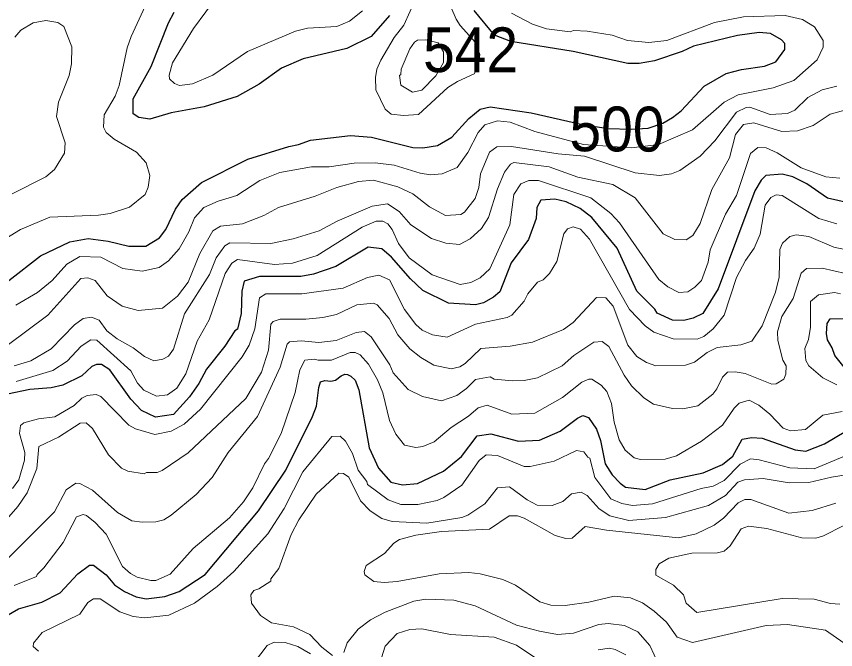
# Model space of a CAD drawing. Extents: x 673.3 to 698.5, y 6984.3 to 7012.3.
# Drawn here: x 690.238 to 691.701, y 6994.327 to 6995.457 of the extents above; entities that cross this region are included whole.
import ezdxf
from ezdxf.enums import TextEntityAlignment as Align

# ---------------------------------------------------------------- set-up
doc = ezdxf.new("R2010")
doc.units = 0
doc.header["$LTSCALE"] = 0.032
doc.layers.add('1', color=7, linetype='Continuous', lineweight=25)
doc.layers.add('2', color=7, linetype='Continuous', lineweight=13)
doc.layers.add('21', color=7, linetype='Continuous')
doc.layers.add('61', color=7, linetype='Continuous')

msp = doc.modelspace()

# ---------------------------------------------------------------- linework, layer by layer
at = {"layer": '1'}
for points in [[(690.9046, 6995.4588), (690.8716, 6995.4215), (690.8281, 6995.4003), (690.7503, 6995.3815), (690.7115, 6995.3646), (690.6715, 6995.3363), (690.6323, 6995.3145), (690.5737, 6995.2958), (690.5143, 6995.2851), (690.4766, 6995.2741), (690.4569, 6995.2766), (690.4465, 6995.2836), (690.4467, 6995.3102), (690.4786, 6995.3676), (690.5096, 6995.4458), (690.52, 6995.4649)], [(691.5326, 6995.3626), (691.5737, 6995.3684), (691.5942, 6995.3762), (691.61, 6995.3981), (691.6102, 6995.4089), (691.6045, 6995.4157), (691.5845, 6995.4269), (691.5646, 6995.4288), (691.5255, 6995.423), (691.4474, 6995.4043), (691.4271, 6995.3944), (691.3777, 6995.3779), (691.3504, 6995.3735), (691.3298, 6995.3735), (691.2321, 6995.3947), (691.1211, 6995.4128), (691.0919, 6995.4241), (691.0558, 6995.4676)], [(690.2245, 6994.9859), (690.2815, 6995.0299), (690.3338, 6995.0547), (690.3662, 6995.0607), (690.402, 6995.0561), (690.4389, 6995.0469), (690.4691, 6995.0471), (690.4934, 6995.0621), (690.5047, 6995.0768), (690.5224, 6995.1131), (690.534, 6995.1301), (690.5686, 6995.1608), (690.6514, 6995.2023), (690.7245, 6995.2253), (690.7418, 6995.2284), (690.7631, 6995.2361), (690.8347, 6995.2447), (690.8724, 6995.2415), (690.946, 6995.2235), (690.9639, 6995.2228), (690.9903, 6995.2268), (691.0157, 6995.2416), (691.0458, 6995.2748), (691.066, 6995.2917), (691.0839, 6995.2959), (691.1572, 6995.2852), (691.249, 6995.2643), (691.2949, 6995.2569), (691.3361, 6995.2562), (691.3662, 6995.258), (691.3923, 6995.2664), (691.4099, 6995.2769), (691.4251, 6995.289), (691.4664, 6995.333), (691.5055, 6995.3552), (691.5326, 6995.3626)], [(691.7233, 6995.1244), (691.6866, 6995.1325), (691.6493, 6995.1584), (691.6246, 6995.1707), (691.6054, 6995.1755), (691.5763, 6995.173), (691.5681, 6995.1651), (691.5567, 6995.1457), (691.4912, 6994.9709), (691.4641, 6994.927), (691.4468, 6994.9184), (691.4297, 6994.9142), (691.4099, 6994.915), (691.3823, 6994.9272), (691.3781, 6994.9344), (691.3462, 6994.967), (691.3109, 6995.0435), (691.2656, 6995.0983), (691.2446, 6995.1144), (691.2196, 6995.1265), (691.1998, 6995.1307), (691.1743, 6995.1292), (691.1673, 6995.116), (691.1664, 6995.0965), (691.1525, 6995.0591), (691.1217, 6995.0175), (691.1013, 6994.9653), (691.0901, 6994.9558), (691.072, 6994.9461), (691.0578, 6994.9426), (691.0095, 6994.9453), (690.9639, 6994.9677), (690.942, 6994.9887), (690.908, 6995.0275), (690.8906, 6995.0425), (690.866, 6995.0451), (690.8087, 6995.0109), (690.7685, 6994.9972), (690.7463, 6994.9929), (690.6721, 6994.9931), (690.645, 6994.9844), (690.6404, 6994.9665), (690.6395, 6994.9268), (690.6331, 6994.8989), (690.628, 6994.8958), (690.6102, 6994.8685), (690.5779, 6994.8276), (690.564, 6994.802), (690.547, 6994.7783), (690.5187, 6994.7463), (690.4865, 6994.7415), (690.4614, 6994.7536), (690.4427, 6994.774), (690.4053, 6994.8265), (690.3903, 6994.8359), (690.3813, 6994.8359), (690.373, 6994.8321), (690.3549, 6994.8156), (690.321, 6994.7987), (690.3004, 6994.7944), (690.2619, 6994.7912), (690.222, 6994.7827)], [(691.7164, 6994.8308), (691.6993, 6994.852), (691.6949, 6994.8658), (691.6864, 6994.8798), (691.6844, 6994.8911), (691.686, 6994.9089), (691.6914, 6994.9174), (691.7197, 6994.9181)], [(690.4134, 6994.4422), (690.4313, 6994.4302), (690.4521, 6994.421), (690.4699, 6994.4174), (690.503, 6994.4217), (690.529, 6994.4305), (690.5754, 6994.4609), (690.6704, 6994.5745), (690.7195, 6994.6473), (690.7671, 6994.7428), (690.774, 6994.7614), (690.7781, 6994.795), (690.7813, 6994.8049), (690.7887, 6994.8073), (690.7998, 6994.8059), (690.8082, 6994.8077), (690.8179, 6994.8156), (690.8244, 6994.8184), (690.8295, 6994.8177), (690.8356, 6994.8152), (690.8428, 6994.8077), (690.8497, 6994.7908), (690.8678, 6994.687), (690.8845, 6994.6505), (690.9067, 6994.6259), (690.9275, 6994.621), (690.9545, 6994.6232), (691.0006, 6994.6455), (691.0328, 6994.6714), (691.0606, 6994.7087), (691.085, 6994.7121), (691.1349, 6994.6991), (691.1724, 6994.7008), (691.2093, 6994.7169), (691.2399, 6994.7402), (691.2493, 6994.7446), (691.2598, 6994.741), (691.2742, 6994.7205), (691.2812, 6994.7002), (691.2896, 6994.6582), (691.3019, 6994.6386), (691.316, 6994.6236), (691.3258, 6994.617), (691.361, 6994.6128), (691.4053, 6994.6299), (691.4644, 6994.6424), (691.4987, 6994.6572), (691.5173, 6994.6722), (691.5343, 6994.7026), (691.5516, 6994.7056), (691.5695, 6994.704), (691.6285, 6994.6836), (691.6477, 6994.6813), (691.6808, 6994.6941), (691.7191, 6994.7168)], [(690.2033, 6994.3776), (690.2422, 6994.3994), (690.2835, 6994.4117), (690.3164, 6994.4283), (690.3477, 6994.4619), (690.3686, 6994.4776), (690.3758, 6994.4775), (690.3985, 6994.4602), (690.4134, 6994.4422)]]:
    msp.add_lwpolyline(points, dxfattribs=at)
at = {"layer": '2'}
for points in [[(691.0626, 6995.3684), (691.0654, 6995.3894), (691.0581, 6995.4106), (691.0306, 6995.4408), (691.0233, 6995.4522), (691.0043, 6995.4972), (690.9997, 6995.5029), (690.971, 6995.5045), (690.9525, 6995.4925), (690.9302, 6995.4418), (690.9127, 6995.4196), (690.8887, 6995.3791), (690.8819, 6995.3631), (690.8792, 6995.3485), (690.8802, 6995.3264), (690.8967, 6995.2916), (690.9071, 6995.2827), (690.9293, 6995.2806), (690.9564, 6995.282), (691.0085, 6995.3301), (691.0258, 6995.341), (691.0556, 6995.3548)], [(690.9244, 6995.3343), (690.9222, 6995.352), (690.9245, 6995.3533), (690.9253, 6995.3631), (690.9407, 6995.3993), (690.9488, 6995.4112), (690.9543, 6995.4149), (690.9691, 6995.4157), (690.9911, 6995.4101), (691.001, 6995.3943), (691.001, 6995.3751), (690.9872, 6995.3514), (690.9619, 6995.3256), (690.9453, 6995.3221)]]:
    msp.add_lwpolyline(points, close=True, dxfattribs=at)
for points in [[(690.8564, 6995.4673), (690.8327, 6995.4488), (690.8102, 6995.4393), (690.7581, 6995.4361), (690.7363, 6995.4307), (690.651, 6995.3945), (690.5887, 6995.3521), (690.5529, 6995.3367), (690.5295, 6995.3337), (690.5203, 6995.3376), (690.5115, 6995.3459), (690.5109, 6995.3526), (690.5171, 6995.3745), (690.5542, 6995.4356), (690.5987, 6995.4957)], [(690.4683, 6995.4758), (690.4428, 6995.4217), (690.436, 6995.4014), (690.4219, 6995.334), (690.4147, 6995.3149), (690.3951, 6995.2816), (690.3936, 6995.2595), (690.3987, 6995.2502), (690.4129, 6995.2379), (690.4525, 6995.2152), (690.4701, 6995.1958), (690.4766, 6995.1732), (690.4734, 6995.1523), (690.4683, 6995.1391), (690.4401, 6995.1165), (690.4054, 6995.1055), (690.3849, 6995.1023), (690.2976, 6995.0989), (690.2454, 6995.0769), (690.2114, 6995.0559)], [(691.0972, 6995.2707), (691.1197, 6995.2684), (691.1637, 6995.2521), (691.2507, 6995.2284), (691.3363, 6995.2228), (691.3847, 6995.2286), (691.4452, 6995.2547), (691.5017, 6995.3042), (691.5269, 6995.3171), (691.5895, 6995.3295), (691.6262, 6995.3431), (691.6678, 6995.3797), (691.6784, 6995.4024), (691.6785, 6995.4141), (691.6633, 6995.4388), (691.6417, 6995.4515), (691.6106, 6995.4589), (691.5362, 6995.4564), (691.4848, 6995.4466), (691.3998, 6995.4141), (691.3671, 6995.4109), (691.3292, 6995.414), (691.3017, 6995.4241), (691.2572, 6995.4312), (691.2327, 6995.432), (691.2272, 6995.4296), (691.1847, 6995.435), (691.1594, 6995.4433), (691.1219, 6995.4628)], [(690.2307, 6995.1405), (690.2907, 6995.1708), (690.3064, 6995.1837), (690.3243, 6995.2133), (690.325, 6995.2314), (690.3097, 6995.2784), (690.3131, 6995.3043), (690.3322, 6995.3516), (690.3364, 6995.3728), (690.3373, 6995.4027), (690.3228, 6995.4391), (690.3121, 6995.4466), (690.291, 6995.45), (690.2684, 6995.4459), (690.2459, 6995.4325), (690.2355, 6995.4203)], [(691.7028, 6995.3326), (691.677, 6995.3261), (691.6513, 6995.3125), (691.6282, 6995.2896), (691.6147, 6995.2838), (691.5838, 6995.2822), (691.5479, 6995.2953), (691.541, 6995.2948), (691.524, 6995.2863), (691.4855, 6995.2351), (691.459, 6995.2075), (691.4225, 6995.1819), (691.408, 6995.1763), (691.3864, 6995.1732), (691.3431, 6995.178), (691.2523, 6995.208), (691.2055, 6995.2122), (691.122, 6995.2251), (691.096, 6995.2243), (691.0828, 6995.2148), (691.067, 6995.176), (691.0637, 6995.1519), (691.0572, 6995.1323), (691.0384, 6995.1078), (691.0317, 6995.1039), (691.0044, 6995.1017), (690.9755, 6995.117), (690.9462, 6995.1407), (690.9195, 6995.1533), (690.8757, 6995.1649), (690.8493, 6995.1624), (690.8102, 6995.1518), (690.7717, 6995.1366), (690.7064, 6995.116), (690.6799, 6995.1021), (690.6418, 6995.087), (690.6024, 6995.0826), (690.5891, 6995.0746), (690.5659, 6995.034), (690.545, 6994.9826), (690.5261, 6994.9579), (690.499, 6994.9362), (690.4555, 6994.9321), (690.4268, 6994.9399), (690.4003, 6994.9586), (690.3786, 6994.9859), (690.3656, 6994.9906), (690.3531, 6994.9891), (690.2945, 6994.9241), (690.2219, 6994.8697)], [(690.234, 6994.8335), (690.264, 6994.8425), (690.3002, 6994.8638), (690.342, 6994.9065), (690.3571, 6994.9177), (690.3723, 6994.9205), (690.3862, 6994.9148), (690.3995, 6994.896), (690.4183, 6994.8814), (690.4467, 6994.8656), (690.4667, 6994.8502), (690.4835, 6994.8425), (690.4999, 6994.845), (690.51, 6994.8506), (690.5188, 6994.8634), (690.5383, 6994.9265), (690.583, 6994.9966), (690.5948, 6995.0265), (690.6103, 6995.0476), (690.6193, 6995.053), (690.6926, 6995.0518), (690.7326, 6995.0599), (690.779, 6995.0743), (690.8111, 6995.0915), (690.8734, 6995.1183), (690.9006, 6995.1226), (690.9218, 6995.1089), (690.9424, 6995.0853), (690.9793, 6995.0606), (691.0048, 6995.0522), (691.0296, 6995.0501), (691.0486, 6995.06), (691.0688, 6995.0789), (691.081, 6995.0984), (691.0973, 6995.1496), (691.1099, 6995.179), (691.1204, 6995.1937), (691.1263, 6995.1966), (691.1897, 6995.1886), (691.2405, 6995.1702), (691.3034, 6995.1571), (691.3431, 6995.1331), (691.3927, 6995.0691), (691.4138, 6995.0589), (691.4341, 6995.0583), (691.4462, 6995.0662), (691.4588, 6995.0878), (691.4798, 6995.1484), (691.5114, 6995.205), (691.5221, 6995.2462), (691.5364, 6995.2643), (691.5549, 6995.2675), (691.6051, 6995.2521), (691.6327, 6995.2528), (691.661, 6995.2628), (691.6914, 6995.2828), (691.724, 6995.2918)], [(690.2369, 6994.9416), (690.2761, 6994.9643), (690.3021, 6994.9855), (690.3282, 6995.0148), (690.3513, 6995.0289), (690.3888, 6995.0272), (690.4283, 6995.0074), (690.4625, 6995.0025), (690.4932, 6995.0087), (690.51, 6995.0208), (690.529, 6995.0423), (690.5459, 6995.0726), (690.5561, 6995.0975), (690.5727, 6995.116), (690.5982, 6995.1272), (690.632, 6995.1374), (690.6731, 6995.1644), (690.7083, 6995.1784), (690.7652, 6995.1886), (690.7966, 6995.1886), (690.8412, 6995.195), (690.8789, 6995.1959), (690.9128, 6995.1918), (690.9589, 6995.1776), (690.9777, 6995.1747), (690.9982, 6995.1764), (691.0254, 6995.1877), (691.0444, 6995.2144), (691.0627, 6995.2502), (691.0747, 6995.2635), (691.0972, 6995.2707)], [(691.7085, 6995.1682), (691.6834, 6995.1708), (691.6393, 6995.1871), (691.5964, 6995.2137), (691.5767, 6995.2225), (691.5619, 6995.2232), (691.5492, 6995.2126), (691.5242, 6995.1378), (691.5042, 6995.1044), (691.4767, 6995.0403), (691.4735, 6995.0186), (691.4612, 6994.986), (691.4498, 6994.9736), (691.4373, 6994.9658), (691.4209, 6994.9646), (691.4015, 6994.9745), (691.3851, 6994.9878), (691.315, 6995.0889), (691.2997, 6995.1056), (691.2641, 6995.1331), (691.1703, 6995.1645), (691.1529, 6995.1642), (691.1388, 6995.1584), (691.1266, 6995.1393), (691.1191, 6995.0851), (691.0834, 6995.0064), (691.066, 6994.9905), (691.0493, 6994.9823), (691.0308, 6994.9785), (690.9806, 6994.9961), (690.9396, 6995.0262), (690.9202, 6995.0516), (690.9091, 6995.0767), (690.9015, 6995.0869), (690.8927, 6995.0916), (690.8805, 6995.0916), (690.8555, 6995.0807), (690.7753, 6995.0304), (690.7313, 6995.0166), (690.6988, 6995.0143), (690.6331, 6995.0233), (690.6226, 6995.0169), (690.6111, 6994.9984), (690.5824, 6994.9155), (690.5609, 6994.8774), (690.5406, 6994.8189), (690.5246, 6994.7935), (690.5082, 6994.7817), (690.4881, 6994.779), (690.4655, 6994.7902), (690.4542, 6994.8026), (690.4424, 6994.8245), (690.3817, 6994.879), (690.3713, 6994.8799), (690.354, 6994.8684), (690.3287, 6994.8419), (690.3031, 6994.8249), (690.2377, 6994.8055)], [(690.2423, 6994.6297), (690.2526, 6994.665), (690.2534, 6994.6787), (690.2437, 6994.7126), (690.2454, 6994.7269), (690.2513, 6994.7318), (690.2776, 6994.7389), (690.3067, 6994.7426), (690.3412, 6994.7625), (690.3551, 6994.7759), (690.3648, 6994.7806), (690.3808, 6994.7822), (690.389, 6994.7787), (690.439, 6994.7275), (690.4509, 6994.7209), (690.4854, 6994.7106), (690.5147, 6994.7165), (690.538, 6994.7294), (690.5668, 6994.7559), (690.6413, 6994.8492), (690.6536, 6994.87), (690.6639, 6994.8994), (690.6721, 6994.9546), (690.6833, 6994.962), (690.7477, 6994.9622), (690.8219, 6994.972), (690.8653, 6994.9912), (690.8854, 6994.9954), (690.9041, 6994.9867), (690.9309, 6994.9339), (690.9511, 6994.9072), (690.9629, 6994.8971), (690.9812, 6994.889), (691.0076, 6994.8848), (691.0581, 6994.9075), (691.1144, 6994.9195), (691.1226, 6994.9241), (691.145, 6994.9489), (691.1514, 6994.9619), (691.1686, 6994.983), (691.179, 6994.9869), (691.1903, 6994.9984), (691.2029, 6995.0198), (691.2158, 6995.0689), (691.2222, 6995.0779), (691.2323, 6995.0817), (691.2454, 6995.0777), (691.2614, 6995.0593), (691.3331, 6994.9339), (691.3608, 6994.9046), (691.3764, 6994.8934), (691.4108, 6994.8817), (691.4539, 6994.8808), (691.4655, 6994.8857), (691.4824, 6994.8994), (691.5019, 6994.9239), (691.5242, 6994.9912), (691.5402, 6995.0216), (691.5557, 6995.0437), (691.5661, 6995.0685), (691.5753, 6995.1201), (691.5851, 6995.1339), (691.595, 6995.1385), (691.6056, 6995.1378), (691.6708, 6995.0964), (691.7028, 6995.0868)], [(690.4985, 6994.6465), (690.5446, 6994.6783), (690.6478, 6994.7751), (690.6757, 6994.8222), (690.6882, 6994.8614), (690.6925, 6994.9076), (690.6965, 6994.9124), (690.7089, 6994.9165), (690.7551, 6994.9165), (690.7851, 6994.9195), (690.8095, 6994.9249), (690.8459, 6994.9423), (690.8757, 6994.945), (690.8823, 6994.9424), (690.9037, 6994.9179), (690.9191, 6994.8885), (690.9406, 6994.8639), (690.9604, 6994.8485), (690.9838, 6994.8348), (691.0143, 6994.8279), (691.0301, 6994.8319), (691.0394, 6994.8377), (691.0676, 6994.8645), (691.1198, 6994.8685), (691.1596, 6994.8756), (691.2148, 6994.898), (691.2324, 6994.9109), (691.2742, 6994.9555), (691.2907, 6994.9548), (691.3038, 6994.9398), (691.33, 6994.8704), (691.3459, 6994.8502), (691.3633, 6994.8393), (691.3796, 6994.8335), (691.4327, 6994.8343), (691.4492, 6994.8401), (691.4718, 6994.857), (691.4897, 6994.866), (691.5319, 6994.8709), (691.5515, 6994.8775), (691.5696, 6994.9046), (691.5936, 6994.9651), (691.6004, 6994.9915), (691.6013, 6995.041), (691.606, 6995.0523), (691.6192, 6995.0646), (691.6307, 6995.0671), (691.6532, 6995.0646), (691.6976, 6995.0454), (691.7175, 6995.0412)], [(690.8716, 6994.8854), (690.9049, 6994.8351), (690.9111, 6994.8207), (690.9374, 6994.7911), (690.9631, 6994.7786), (690.997, 6994.7707), (691.0245, 6994.7804), (691.042, 6994.7929), (691.0582, 6994.809), (691.0839, 6994.8139), (691.0915, 6994.8097), (691.1238, 6994.8066), (691.145, 6994.8073), (691.1689, 6994.8121), (691.2126, 6994.8333), (691.2334, 6994.8516), (691.2693, 6994.8755), (691.2842, 6994.8766), (691.2959, 6994.8677), (691.3232, 6994.817), (691.3363, 6994.7975), (691.3582, 6994.7765), (691.3755, 6994.7652), (691.4098, 6994.7571), (691.4284, 6994.7565), (691.4549, 6994.7617), (691.4814, 6994.783), (691.4888, 6994.7926), (691.4987, 6994.8131), (691.508, 6994.822), (691.5216, 6994.8227), (691.5396, 6994.8198), (691.5871, 6994.8004), (691.5949, 6994.8014), (691.6086, 6994.8093), (691.6119, 6994.8186), (691.6126, 6994.8331), (691.6068, 6994.8437), (691.5975, 6994.8788), (691.5969, 6994.8939), (691.6051, 6994.9216), (691.625, 6994.9535), (691.6395, 6994.9988), (691.6491, 6995.007), (691.6768, 6995.0078), (691.7188, 6994.998)], [(691.7031, 6994.7992), (691.6783, 6994.8118), (691.6529, 6994.8333), (691.6478, 6994.843), (691.6461, 6994.8641), (691.6527, 6994.8805), (691.6559, 6994.9027), (691.6559, 6994.948), (691.6705, 6994.9604), (691.6988, 6994.9645), (691.7097, 6994.9621)], [(690.2185, 6994.4851), (690.306, 6994.5726), (690.327, 6994.6121), (690.3441, 6994.6237), (690.3512, 6994.6233), (690.3738, 6994.6113), (690.4187, 6994.5714), (690.444, 6994.5566), (690.4626, 6994.5542), (690.487, 6994.555), (690.5015, 6994.5585), (690.5147, 6994.5667), (690.5589, 6994.6038), (690.5878, 6994.6342), (690.6163, 6994.6785), (690.6688, 6994.7431), (690.7094, 6994.8309), (690.7215, 6994.872), (690.7257, 6994.8764), (690.7465, 6994.8782), (690.7779, 6994.8751), (690.8094, 6994.8786), (690.8447, 6994.8929), (690.86, 6994.8945), (690.8716, 6994.8854)], [(690.7112, 6994.7124), (690.7358, 6994.786), (690.7442, 6994.8262), (690.7533, 6994.8433), (690.7699, 6994.8455), (690.7771, 6994.8433), (690.801, 6994.8433), (690.8342, 6994.857), (690.8431, 6994.857), (690.8522, 6994.8529), (690.8668, 6994.8362), (690.8829, 6994.8085), (690.8927, 6994.7854), (690.9043, 6994.736), (690.9157, 6994.7115), (690.9309, 6994.692), (690.9516, 6994.6878), (690.9639, 6994.6894), (690.9843, 6994.6976), (691.0144, 6994.7235), (691.0453, 6994.7437), (691.0628, 6994.7583), (691.0785, 6994.7634), (691.1226, 6994.7473), (691.1637, 6994.7487), (691.2134, 6994.7771), (691.2479, 6994.804), (691.2601, 6994.8098), (691.2658, 6994.8098), (691.2825, 6994.7989), (691.2927, 6994.7875), (691.3007, 6994.7659), (691.3057, 6994.7331), (691.3145, 6994.7013), (691.325, 6994.6829), (691.3413, 6994.6692), (691.3524, 6994.6659), (691.3966, 6994.6665), (691.4167, 6994.6724), (691.4617, 6994.6986), (691.4992, 6994.7272), (691.52, 6994.7579), (691.5288, 6994.7666), (691.5466, 6994.7722), (691.5636, 6994.763), (691.5834, 6994.7471), (691.6072, 6994.7219), (691.6201, 6994.7171), (691.6474, 6994.7195), (691.6778, 6994.7453), (691.7126, 6994.752)], [(690.2246, 6994.5637), (690.2408, 6994.5821), (690.2576, 6994.6069), (690.2746, 6994.6502), (690.2782, 6994.6894), (690.3132, 6994.7061), (690.3522, 6994.7313), (690.3627, 6994.7315), (690.3742, 6994.7217), (690.4027, 6994.6745), (690.4259, 6994.6508), (690.4373, 6994.6453), (690.4663, 6994.6406), (690.4704, 6994.6429), (690.4897, 6994.643), (690.4985, 6994.6465)], [(690.234, 6994.4414), (690.2742, 6994.457), (690.275, 6994.4608), (690.2874, 6994.4725), (690.3217, 6994.5177), (690.3456, 6994.5638), (690.3574, 6994.5678), (690.3632, 6994.5663), (690.3791, 6994.5539), (690.3986, 6994.5327), (690.4279, 6994.4753), (690.442, 6994.4625), (690.4537, 6994.4562), (690.4781, 6994.4499), (690.4871, 6994.4499), (690.5127, 6994.4617), (690.554, 6994.507), (690.6188, 6994.5619), (690.6439, 6994.5903), (690.6603, 6994.6154), (690.6809, 6994.6582), (690.6883, 6994.6681), (690.7112, 6994.7124)], [(690.8653, 6994.6216), (690.8639, 6994.627), (690.8485, 6994.6471), (690.8381, 6994.6766), (690.826, 6994.6991), (690.8163, 6994.7078), (690.8014, 6994.7074), (690.7496, 6994.644), (690.716, 6994.5787), (690.6871, 6994.5333), (690.6262, 6994.466), (690.5965, 6994.4395), (690.5562, 6994.4098), (690.5106, 6994.388), (690.4675, 6994.3832), (690.4467, 6994.3857), (690.4226, 6994.3943), (690.3875, 6994.4173), (690.3759, 6994.4173), (690.3657, 6994.4106), (690.3513, 6994.3901), (690.2844, 6994.357), (690.2685, 6994.3381), (690.2682, 6994.3321), (690.2775, 6994.3239)], [(691.7382, 6994.6812), (691.6624, 6994.6495), (691.6189, 6994.6512), (691.5644, 6994.6658), (691.5492, 6994.6673), (691.5305, 6994.6581), (691.5017, 6994.6289), (691.4822, 6994.6187), (691.4609, 6994.6141), (691.3739, 6994.5867), (691.3384, 6994.5843), (691.3193, 6994.5874), (691.2998, 6994.5959), (691.2712, 6994.6343), (691.2618, 6994.6688), (691.2583, 6994.6701), (691.2516, 6994.6796), (691.238, 6994.6821), (691.1985, 6994.6634), (691.1553, 6994.6535), (691.1446, 6994.6535), (691.0972, 6994.673), (691.0769, 6994.6746), (691.0644, 6994.6645), (691.0333, 6994.6206), (691.0014, 6994.5983), (690.9895, 6994.5932), (690.9552, 6994.5858), (690.9243, 6994.5859), (690.9022, 6994.5941), (690.8653, 6994.6216)], [(690.8027, 6994.3163), (690.7836, 6994.331), (690.7624, 6994.3538), (690.733, 6994.3674), (690.6937, 6994.3748), (690.6738, 6994.3874), (690.6579, 6994.4098), (690.6567, 6994.4245), (690.6623, 6994.4325), (690.671, 6994.4351), (690.6923, 6994.4492), (690.6927, 6994.4532), (690.7065, 6994.4717), (690.7289, 6994.5324), (690.7425, 6994.5587), (690.7732, 6994.604), (690.8139, 6994.6419), (690.8224, 6994.6409), (690.8317, 6994.6346), (690.8524, 6994.5921), (690.8699, 6994.5747), (690.8907, 6994.5606), (690.9092, 6994.5556), (690.9711, 6994.5526), (691.0336, 6994.5627), (691.0444, 6994.5668), (691.0744, 6994.5868), (691.0971, 6994.6158), (691.1187, 6994.6173), (691.1503, 6994.5943), (691.1678, 6994.5846), (691.1946, 6994.5842), (691.2137, 6994.5909), (691.2293, 6994.6047), (691.2467, 6994.6078), (691.2575, 6994.6021), (691.2785, 6994.5781), (691.2976, 6994.5656), (691.3315, 6994.5574), (691.3972, 6994.5623), (691.4739, 6994.5843), (691.5043, 6994.6019), (691.5261, 6994.6255), (691.538, 6994.6298), (691.5715, 6994.6323), (691.6178, 6994.6242), (691.6532, 6994.6248), (691.6936, 6994.6348), (691.7457, 6994.643)], [(690.2313, 6994.6142), (690.2423, 6994.6297)], [(691.7015, 6994.5882), (691.6591, 6994.5752), (691.6172, 6994.5705), (691.5493, 6994.5945), (691.5387, 6994.5948), (691.5267, 6994.5887), (691.501, 6994.5615), (691.4839, 6994.5489), (691.452, 6994.5336), (691.4202, 6994.5265), (691.292, 6994.5401), (691.2537, 6994.5467), (691.2305, 6994.5258), (691.2193, 6994.525), (691.2001, 6994.5304), (691.1447, 6994.5613), (691.133, 6994.5655), (691.1178, 6994.5655), (691.083, 6994.542), (690.9972, 6994.5378), (690.9516, 6994.5312), (690.9223, 6994.5236), (690.9118, 6994.5169), (690.8955, 6994.4983), (690.8629, 6994.4769), (690.8594, 6994.4662), (690.8606, 6994.4602), (690.8763, 6994.4485), (690.8949, 6994.4467), (690.9178, 6994.4482), (690.9929, 6994.4621), (691.0461, 6994.4645), (691.066, 6994.4622), (691.1068, 6994.4516), (691.1292, 6994.442), (691.1727, 6994.4121), (691.1925, 6994.406), (691.2178, 6994.4053), (691.2601, 6994.4116), (691.3057, 6994.4222), (691.3349, 6994.4193), (691.356, 6994.4101), (691.3771, 6994.3955), (691.3987, 6994.3755), (691.4181, 6994.3491), (691.4455, 6994.3392), (691.5771, 6994.3699), (691.6147, 6994.3718), (691.6829, 6994.3613), (691.7164, 6994.3382)], [(691.7083, 6994.4076), (691.692, 6994.4091), (691.6624, 6994.4165), (691.6052, 6994.4181), (691.4532, 6994.3929), (691.434, 6994.4094), (691.4294, 6994.4245), (691.4116, 6994.4417), (691.3799, 6994.4597), (691.3797, 6994.4697), (691.3861, 6994.4798), (691.4032, 6994.4897), (691.4444, 6994.4988), (691.4903, 6994.4996), (691.502, 6994.5026), (691.5127, 6994.512), (691.5323, 6994.5426), (691.5456, 6994.5474), (691.578, 6994.5427), (691.6406, 6994.5265), (691.6655, 6994.5257), (691.6791, 6994.5298), (691.7142, 6994.5476)], [(691.3849, 6994.3007), (691.3693, 6994.334), (691.348, 6994.3583), (691.3238, 6994.3697), (691.2949, 6994.3733), (691.2783, 6994.3718), (691.2327, 6994.3563), (691.2045, 6994.3538), (691.1721, 6994.3594), (691.1314, 6994.3705), (691.0571, 6994.4049), (691.0193, 6994.4148), (690.9692, 6994.4166), (690.9476, 6994.4133), (690.8968, 6994.3937), (690.8706, 6994.3796), (690.8483, 6994.363), (690.8287, 6994.3386), (690.8231, 6994.3218)], [(690.8841, 6994.293), (690.8964, 6994.333), (690.918, 6994.3552), (690.9408, 6994.3627), (690.9623, 6994.3635), (691.0135, 6994.3538), (691.0913, 6994.3488), (691.1312, 6994.3344), (691.1709, 6994.3081)], [(690.6422, 6994.2768), (690.6858, 6994.334), (690.6982, 6994.3399), (690.718, 6994.3391), (690.7408, 6994.3325), (690.7631, 6994.3189)], [(691.2771, 6994.3261), (691.2969, 6994.3292), (691.3075, 6994.3269), (691.3263, 6994.3175)]]:
    msp.add_lwpolyline(points, dxfattribs=at)

# ---------------------------------------------------------------- texts
at = {"layer": '21', "width": 0.95}
msp.add_text('542', height=0.08, dxfattribs=at).set_placement((690.9643, 6995.3577))
at = {"layer": '61', "width": 0.95}
msp.add_text('500', height=0.08, rotation=359.719, dxfattribs=at).set_placement((691.3104, 6995.2163), align=Align.CENTER)

doc.saveas('drawing.dxf')
